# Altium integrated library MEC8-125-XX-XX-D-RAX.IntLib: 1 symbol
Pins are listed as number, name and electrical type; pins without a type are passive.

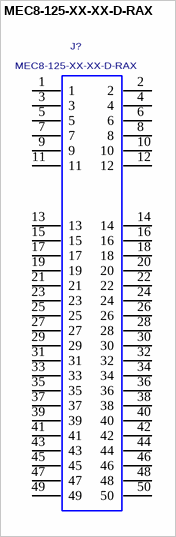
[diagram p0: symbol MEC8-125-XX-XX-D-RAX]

## MEC8-125-XX-XX-D-RAX
designator J?
MICRO EDGE CARD, .8mm PITCH, RIGHT ANGLE, 50 PINS.; MANUFACTURER: SAMTEC
footprint MEC8-125-XX-XX-D-RAX
pins: 1, 2, 3, 4, 5, 6, 7, 8, 9, 10, 11, 12, 13, 14, 15, 16, 17, 18, 19, 20, 21, 22, 23, 24, 25, 26, 27, 28, 29, 30, 31, 32, 33, 34, 35, 36, 37, 38, 39, 40, 41, 42, 43, 44, 45, 46, 47, 48, 49, 50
